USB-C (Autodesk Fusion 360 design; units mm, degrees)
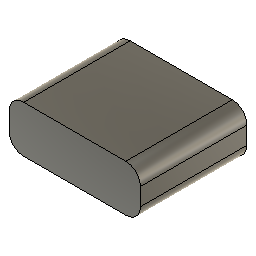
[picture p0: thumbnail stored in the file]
parameter "Ratio" = 1
parameter "fillet" = 1
sketch "Sketch1" plane through (0, 0, 0) normal (0, 0, 1) x axis (1, 0, 0)
  line L1 (-9, 0) -> (0, 0)
  line L2 (-9, 7.3) -> (-9, 0)
  line L3 (0, 7.3) -> (-9, 7.3)
  line L4 (0, 0) -> (0, 7.3)
  point P1 (0, 0)
  point P2 (0, 0)
  point P3 (-9, 0)
  point P5 (0, 7.3)
  horizontal L1
  vertical L2
  horizontal L3
  vertical L4
  coincident P1 P2
  dimension "d1" distance P2 P3 = 9 (= "9 * Ratio")
  dimension "d3" distance P2 P5 = 7.3 (= "7.3 * Ratio")
extrude "Extrude1" new body sketch "Sketch1" along normal blind 3.2 (= "3.2 * Ratio")
fillet "Fillet1" radius 1 (= "fillet")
